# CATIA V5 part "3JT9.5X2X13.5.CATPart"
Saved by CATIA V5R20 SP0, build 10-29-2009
Part number: 3JT9.5X2X13.5
Revision: ANY
Definition: UNKNOWN
Nomenclature: 3JT9.5X2X13.5
Source: Unknown
Bounding box of the stored display mesh (mm): x -6.581 to 6.581, y -1 to 1, z -6.75 to 6.75
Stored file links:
  C:\Users\Utente\Desktop\IO LAVORO\3D X SITO CF\CUMSA\3D files PW\pw081025\pw081025_ejection\3JT9.5X2X13.5.CATPart
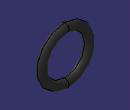
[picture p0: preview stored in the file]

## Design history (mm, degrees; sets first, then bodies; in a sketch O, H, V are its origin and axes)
Body1 "Revolución1" (main body)
  Solid1: solid without history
